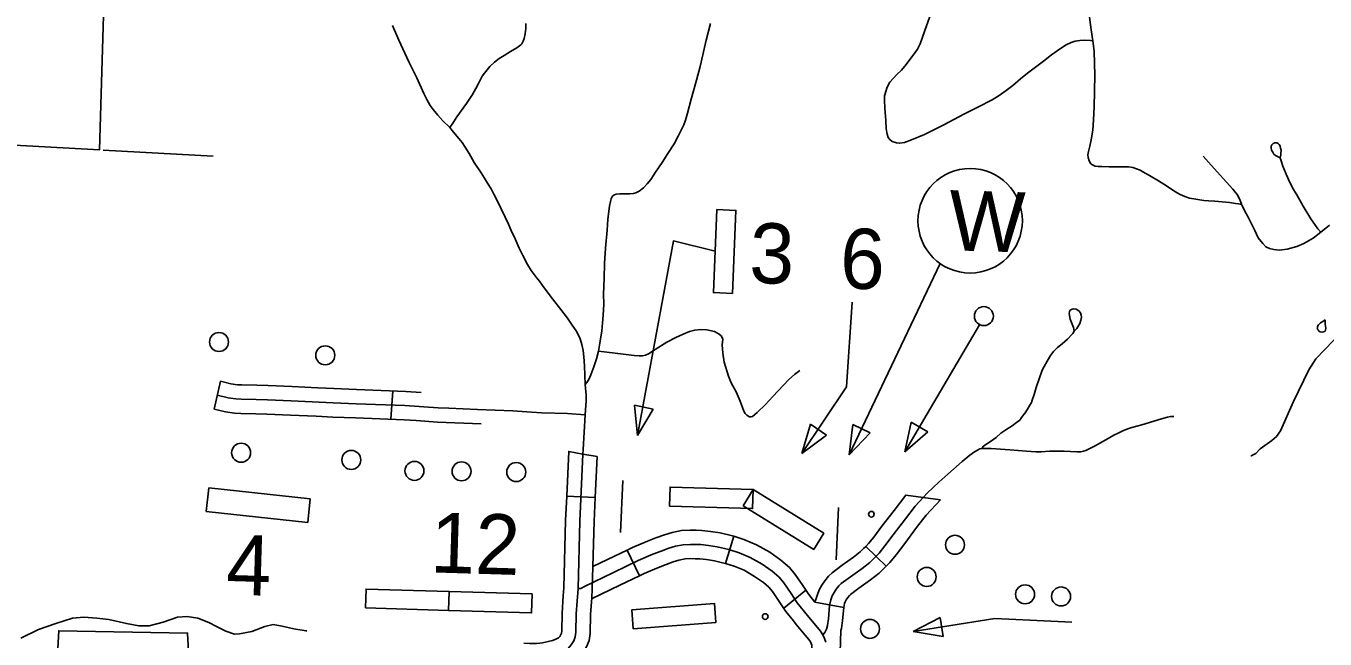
# Model space of a CAD drawing. Extents: x 653372 to 905732, y 627442 to 787275.
# Drawn here: x 690999 to 697843, y 760924 to 764152 of the extents above; entities that cross this region are included whole.
import ezdxf

# ---------------------------------------------------------------- set-up
doc = ezdxf.new("R2010")
doc.units = 0
for name, color, linetype in [('31', 7, 'Continuous'), ('32', 7, 'Continuous'), ('35', 7, 'Continuous'), ('45', 7, 'Continuous'), ('5', 7, 'Continuous'), ('56', 7, 'Continuous'), ('57', 7, 'Continuous'), ('6', 7, 'Continuous')]:
    doc.layers.add(name, color=color, linetype=linetype)

msp = doc.modelspace()

# ---------------------------------------------------------------- linework, layer by layer
at = {"layer": '31'}
msp.add_line((693848.6, 761677.2), (693998.4, 761670.3), dxfattribs=at)
for points in [[(696620.4, 764073.4), (696607.2, 764075.7), (696574.6, 764078.2), (696552.3, 764076.6), (696527.7, 764072.1), (696505.9, 764065.4), (696478.8, 764052.8), (696450, 764033.6), (696402.9, 764000.8), (696359.6, 763966.5), (696310.9, 763930), (696276.7, 763904.3), (696239.4, 763873.5), (696199, 763839), (696163.3, 763811.9), (696126.9, 763786.9), (696090.5, 763764.3), (696013.6, 763725), (695943.1, 763689.9), (695831.3, 763630.1), (695733.3, 763581.8), (695664.1, 763552.7), (695627.3, 763539.6), (695601.9, 763534.5), (695585.6, 763536.4), (695563.6, 763544.5), (695551.2, 763553.8), (695542.6, 763564.5), (695535.7, 763582.5), (695532.1, 763610.1), (695529, 763655.5), (695523.5, 763719.6), (695521.8, 763762), (695523.2, 763784.3), (695529.9, 763807.8), (695537.2, 763829.9), (695551.4, 763857), (695587.5, 763896.8), (695612.7, 763920.5), (695636.6, 763948.8), (695662.1, 763982.2), (695679.2, 764005), (695695.5, 764030.5), (695709.7, 764059), (695734, 764123.7), (695761.6, 764201.6)], [(696599.3, 764224.9), (696612, 764131.4), (696620.4, 764073.4), (696626.3, 764018.9), (696629.2, 763955.2), (696630.5, 763893), (696626.6, 763727.1), (696623.5, 763658.2), (696619.2, 763603.2), (696610.7, 763552.7), (696604.3, 763519.2), (696597, 763490.7), (696594.4, 763474.2), (696595.6, 763460.2), (696601, 763443), (696609.6, 763426.7), (696618, 763421), (696631.7, 763414.2), (696648.2, 763412.7), (696666.9, 763411.6), (696706.4, 763410.9), (696783.7, 763411.3), (696808.8, 763410), (696830.1, 763406.7), (696849.7, 763400.7), (696869.2, 763393.2), (696884, 763384.7), (696918.7, 763365.5), (696965.4, 763336.2), (697007.5, 763311.2), (697051.5, 763281.5), (697080.4, 763264.6), (697104.1, 763253.7), (697129.8, 763246.5), (697163.3, 763240.2), (697204.3, 763234.1), (697229.4, 763231.2), (697262.5, 763229.1), (697301.4, 763226.4), (697339.3, 763222.6), (697371.8, 763217.8), (697387.4, 763215.5), (697395.9, 763214.2), (697403.2, 763214.8)], [(692930.7, 764154.9), (692964.1, 764077.8), (693017.3, 763963.5), (693058.4, 763879.9), (693095.8, 763797.6), (693112, 763765.6), (693129.6, 763733.5), (693144.3, 763712.6), (693168.9, 763683.6), (693194.9, 763652.6), (693231.7, 763617.7), (693251.1, 763593.4), (693279.4, 763560.5), (693297.7, 763539.1), (693314, 763513.7), (693333.5, 763480.6), (693361.3, 763433.8), (693396.8, 763379.4), (693414.9, 763350.6), (693431.8, 763325.2), (693449.9, 763294.5), (693463.5, 763267.6), (693482.8, 763230.4), (693502.4, 763189), (693524.2, 763145.7), (693541.2, 763109), (693555.5, 763075.2), (693576.4, 763031.4), (693597.2, 762982), (693616.9, 762942.9), (693642.5, 762897.2), (693661, 762864.1), (693687.8, 762829.4), (693704.8, 762808.5), (693729.4, 762773.2), (693772.7, 762714.8), (693816.5, 762659.2), (693851.8, 762613.2), (693876.2, 762577.1), (693897.6, 762547.8), (693912.1, 762521.4), (693920, 762504.8), (693927.9, 762475.8), (693934.4, 762444), (693938.9, 762410.5), (693941.2, 762362.1), (693945.7, 762264.8), (693950, 762208), (693950.4, 762175.8), (693949.4, 762155.2), (693945, 762104.3), (693935, 761922.7), (693933.8, 761897.8)], [(693633.6, 764165.9), (693632.8, 764138.9), (693629.9, 764111), (693624.5, 764086.2), (693619.3, 764072.8), (693612.2, 764058.9), (693607.3, 764052.9), (693585.2, 764037.4), (693551.5, 764017.5), (693518.5, 763997.5), (693492.4, 763980.8), (693467.5, 763961.3), (693443.9, 763939), (693415.8, 763904.7), (693402.5, 763887.4), (693393.9, 763871.4), (693383.8, 763849.4), (693370.2, 763823.5), (693352.4, 763792.3), (693320.6, 763744.7), (693269.1, 763673.3), (693251.5, 763646.1), (693231.7, 763617.7)], [(697867, 763102.9), (697821.9, 763065.8), (697780.9, 763035.7), (697732.5, 763007), (697694.7, 762990.7), (697644.4, 762977.9), (697601.4, 762972.1), (697573.7, 762974.5), (697551.7, 762980.7), (697531.4, 762989.3), (697515.2, 763006.4), (697491.5, 763036.5), (697472.9, 763075.9), (697437.7, 763145.1), (697419.8, 763181.4), (697403.2, 763214.8), (697393.7, 763238.5), (697381, 763264.2), (697358.1, 763292.7), (697323.5, 763329.4), (697243.4, 763419), (697202, 763466.2)], [(697843.3, 762605), (697844.1, 762582.8), (697847.4, 762561.2), (697846.3, 762551.4), (697842.1, 762544.3), (697835.7, 762541), (697827.7, 762539.2), (697818.2, 762541.1), (697810.8, 762545.7), (697806.7, 762551.8), (697802.8, 762557), (697803, 762563), (697804.4, 762569.7), (697809.8, 762577.8), (697819.3, 762588.7), (697832.2, 762596.6), (697843.3, 762605)], [(694008.3, 761886), (693933.8, 761897.8), (693859.4, 761912), (693848.6, 761677.2)], [(693908, 761190.5), (693917.6, 761545), (693933.8, 761897.8)], [(693998.4, 761670.3), (694008.3, 761886)], [(693830.1, 761151.3), (693833.1, 761194.1), (693842.6, 761547.8), (693848.6, 761677.2)], [(693979.8, 761141), (693982.9, 761187), (693992.5, 761542.3), (693998.4, 761670.3)], [(692564.8, 760837.9), (692592.5, 760840.5), (692646.4, 760843.5), (692695.7, 760846), (692731.5, 760845.6), (692839.5, 760842.9), (693047.8, 760839.5), (693324.6, 760833.8), (693650.7, 760826), (693691.9, 760826.1), (693714.6, 760828.1), (693733.9, 760830.8), (693767.3, 760837.8), (693794.8, 760844.3), (693816.9, 760852.2), (693839.9, 760863.5), (693856.1, 760875), (693872.6, 760893.8), (693885.2, 760915.3), (693893.1, 760935), (693896.5, 760959.5), (693898.8, 761057.4), (693908, 761190.5)], [(693618.6, 760751.7), (693649.9, 760751), (693695.3, 760751.1), (693723.1, 760753.5), (693746.8, 760756.9), (693783.6, 760764.6), (693816.2, 760772.3), (693846.3, 760783.1), (693878.2, 760798.8), (693906.6, 760818.8), (693933.7, 760849.7), (693952.8, 760882.2), (693966.2, 760915.6), (693971.4, 760953.5), (693973.8, 761054), (693979.8, 761141)], [(693622.1, 760901.7), (693651.6, 760901), (693688.6, 760901.1), (693706, 760902.6), (693721, 760904.7), (693751.1, 760911), (693773.4, 760916.3), (693787.6, 760921.4), (693801.5, 760928.2), (693805.7, 760931.2), (693811.6, 760937.9), (693817.7, 760948.4), (693820.1, 760954.4), (693821.7, 760965.5), (693823.9, 761060.9), (693830.1, 761151.3)]]:
    msp.add_lwpolyline(points, dxfattribs=at)
at = {"layer": '32'}
for p, q in [((694729, 761465), (694684.2, 761321.9)), ((694166.3, 761392.6), (694231.8, 761257.7)), ((695531, 761307.1), (695423.6, 761411.8)), ((695108.9, 761180.9), (694991.7, 761087.3)), ((695307.7, 761089.8), (695156.2, 761117.5))]:
    msp.add_line(p, q, dxfattribs=at)
for points in [[(694606.5, 764166), (694583.2, 764077.1), (694550.5, 763939.3), (694531.6, 763867.6), (694503.5, 763767), (694484.1, 763693.3), (694473.6, 763657.2), (694464.5, 763631.4), (694453.5, 763607.3), (694435.7, 763572.4), (694413.8, 763532.2), (694381.7, 763480.1), (694350.8, 763432.7), (694315.3, 763382.6), (694291.1, 763344.5), (694271.6, 763320.4), (694252.3, 763300.4), (694229.2, 763283.3), (694212.7, 763273.5), (694199.8, 763269.9), (694181.5, 763268), (694128.4, 763268.1), (694109.6, 763267.3), (694100.2, 763264.1), (694093.7, 763260.4), (694086.5, 763251.7), (694082.8, 763242), (694078.9, 763227.9), (694074.3, 763204.4), (694071, 763177.4), (694065.3, 763133.1), (694060.6, 763076.6), (694053.4, 762982.8), (694048.1, 762904.2), (694045.6, 762822.5), (694042.6, 762739.9), (694043, 762688.2), (694040.3, 762628.7), (694036.6, 762589), (694033.4, 762547.9), (694024.4, 762492.1), (694015.6, 762439.7), (694005.4, 762400.1), (693991.3, 762358), (693975.8, 762315.2), (693964.5, 762290.2), (693954.3, 762274.7), (693945.7, 762264.8)], [(696521.8, 762545.3), (696517.4, 762564.6), (696500.1, 762607.9), (696494.9, 762639.2), (696497, 762649), (696501.5, 762655.1), (696511, 762661.6), (696519.8, 762663.2), (696532.7, 762660.4), (696546.1, 762651.9), (696554.9, 762641.3), (696559.1, 762629.8), (696560, 762618.6), (696557.7, 762602.5), (696551.6, 762585.3), (696535.3, 762559.1), (696521.8, 762545.3)], [(696036.2, 761927.5), (696041.2, 761936.7), (696051.4, 761944.4), (696086.2, 761967.6), (696110.3, 761984.9), (696135.9, 762008.3), (696161.2, 762026.2), (696194.8, 762047.5), (696218.8, 762063.6), (696234.8, 762076.8), (696245.1, 762091.4), (696263.2, 762115), (696275.6, 762134.5), (696288.7, 762155.9), (696296.5, 762169.9), (696301.2, 762182.2), (696310.8, 762211.7), (696321.2, 762248), (696337.5, 762294.1), (696353.8, 762339.6), (696364.3, 762359.4), (696379.4, 762388.2), (696397.1, 762416.8), (696412.6, 762437.5), (696433.1, 762458.6), (696457.9, 762479), (696486.6, 762503.6), (696511.4, 762529.4), (696514.7, 762533.7), (696521.8, 762545.3)], [(695726.4, 761669.3), (695748.8, 761693.8), (695808.8, 761750.2), (695855.3, 761792.6), (695931.1, 761859.2), (695972.5, 761892.8), (695996.6, 761910.7), (696011.8, 761919.5), (696025.6, 761925.3), (696036.2, 761927.5), (696047.4, 761927.2), (696085.3, 761927.3), (696182.2, 761920.6), (696270.7, 761913.6), (696319.6, 761909.1), (696348.2, 761909.4), (696391.7, 761913.1), (696448.3, 761913.9), (696469.3, 761912.6), (696536.3, 761909.4), (696556.2, 761910.6), (696570.5, 761912.7), (696583.7, 761916.6), (696628.7, 761939.5), (696688.1, 761972.5), (696731.1, 761998.5), (696753.1, 762009), (696781.4, 762021.9), (696804.6, 762030.5), (696825.3, 762037.3), (696878.6, 762052.5), (696941.2, 762071.1), (696981.3, 762084.2), (697013.9, 762093.1), (697030.1, 762096.4), (697046.8, 762095.8)], [(695197.8, 760945.9), (695208, 760957.9), (695216.1, 760976.2), (695222.2, 760995.9), (695227, 761030.6), (695233.5, 761101.2), (695240, 761131.4), (695246.8, 761151.7), (695256.6, 761168.8), (695268.3, 761187), (695282.5, 761204.6), (695294.6, 761216.1), (695343.5, 761252.5), (695404.4, 761295.3), (695444.5, 761327.1), (695465.2, 761347.1), (695494.1, 761376.7), (695525, 761414.2), (695568.9, 761472.5), (695632.3, 761556.3), (695684.6, 761624.3), (695726.4, 761669.3)], [(695423.6, 761411.8), (695438.2, 761426.8), (695466.1, 761460.7), (695509.1, 761517.7), (695572.7, 761601.8), (695634.3, 761681.9), (695817.3, 761656.9)], [(695531, 761307.1), (695550, 761326.6), (695583.9, 761367.8), (695628.8, 761427.3), (695691.9, 761510.8), (695741.9, 761575.8), (695817.3, 761656.9)], [(694729, 761465), (694722.3, 761467.1), (694656.3, 761482.8), (694605.6, 761490.9), (694560.8, 761496), (694529.8, 761496.9), (694499.3, 761497.8), (694452.9, 761495.2), (694403.9, 761485.5), (694363, 761473.7), (694318.3, 761457.6), (694274.2, 761439.6), (694194.6, 761406.4), (694166.3, 761392.6)], [(695156.2, 761117.5), (695123.9, 761157.9), (695092.4, 761206.4), (695051.2, 761264.6), (695021.2, 761301.5), (694977.1, 761340.1), (694918.3, 761381.2), (694848.4, 761421), (694781.9, 761448.5), (694729, 761465)], [(695063, 761114), (695030.3, 761164.3), (694991.4, 761219.3), (694967.1, 761249.3), (694930.8, 761280.9), (694878.1, 761317.7), (694815.4, 761353.5), (694756.4, 761377.9), (694702.4, 761394.8), (694641.7, 761409.2), (694595.5, 761416.6), (694555.4, 761421.1), (694527.5, 761422), (694500.3, 761422.8), (694462.4, 761420.6), (694421.6, 761412.5), (694386.1, 761402.3), (694345.2, 761387.6), (694302.8, 761370.2), (694225.4, 761338), (694095.3, 761274.8), (693941.7, 761201), (693922.1, 761191), (693908, 761190.5)], [(694166.3, 761392.6), (694062.7, 761342.3), (693986.1, 761305.6)], [(695156.2, 761117.5), (695178, 761182.6), (695192.5, 761207.7), (695207.4, 761231), (695227.3, 761255.7), (695246.4, 761273.6), (695299.5, 761313.2), (695359.5, 761355.5), (695395, 761383.6), (695412.3, 761400.3), (695423.6, 761411.8)], [(694684.2, 761321.9), (694682.5, 761322.4), (694627.1, 761335.6), (694585.3, 761342.3), (694550.1, 761346.2), (694525.3, 761347), (694501.4, 761347.7), (694471.9, 761346), (694439.3, 761339.6), (694409.2, 761330.9), (694372, 761317.5), (694331.4, 761300.9), (694256.3, 761269.6), (694231.8, 761257.7)], [(695042.7, 761019.2), (695002.2, 761070), (694968.2, 761122.2), (694931.6, 761174), (694912.9, 761197), (694884.6, 761221.8), (694838, 761254.3), (694782.4, 761286), (694730.8, 761307.3), (694684.2, 761321.9)], [(695292.3, 760968.7), (695295.7, 760979.5), (695301.5, 761022), (695307.7, 761089.8), (695312.4, 761111.5), (695315.5, 761120.7), (695320.7, 761129.8), (695329.2, 761143.1), (695337.7, 761153.5), (695342.9, 761158.5), (695387.5, 761191.7), (695449.3, 761235.2), (695493.9, 761270.5), (695518.1, 761293.9), (695531, 761307.1)], [(694231.8, 761257.7), (694127.9, 761207.3), (693979.4, 761135.9)], [(695212.6, 760907.9), (695206.3, 760927.5), (695197.8, 760945.9), (695185.2, 760965.7), (695116, 761047.7), (695063, 761114)], [(695126.2, 760578.7), (695131, 760686.3), (695138.9, 760858.5), (695139.7, 760885.2), (695139, 760892), (695136.3, 760900.1), (695131.8, 760909.8), (695124.6, 760921.2), (695058, 761000.1), (695042.7, 761019.2)], [(695276.1, 760572.1), (695280.8, 760679.5), (695288.8, 760852.8), (695292.3, 760968.7)]]:
    msp.add_lwpolyline(points, dxfattribs=at)
at = {"layer": '35'}
for points in [[(697934.2, 762543.4), (697795.8, 762399.3), (697757.6, 762341.9), (697677.3, 762175.4), (697608.8, 762020), (697587.3, 761991.3), (697563.7, 761969.8), (697501.3, 761925.1), (697479.2, 761901.9), (697453.4, 761889.3), (697452, 761889.1)], [(692479.2, 760967), (692475.2, 760966.7), (692410.4, 760978.7), (692349, 760992.2), (692302.5, 761000.3), (692257.1, 760990), (692189.5, 760963.6), (692124, 760952.2), (692097.2, 760949.6), (692052.6, 760966), (692003.2, 760990.9), (691962, 761010.5), (691904.3, 761034), (691849.4, 761042.3), (691798.4, 761038.8), (691722.4, 761012.7), (691648.4, 760993.2), (691594.9, 760993.1), (691528.5, 761005.1), (691435.6, 761026.3), (691372.4, 761034.9), (691304, 761038.6), (691245.4, 761033.7), (691156.1, 761006.3), (691064.9, 760974), (690971.7, 760928.3)]]:
    msp.add_lwpolyline(points, dxfattribs=at)
at = {"layer": '45'}
for p, q in [((691990.5, 762135.1), (692023.5, 762281.4)), ((692921.7, 762081.1), (692931.8, 762230.8))]:
    msp.add_line(p, q, dxfattribs=at)
for points in [[(697607.5, 763458.2), (697595.9, 763462.6), (697582.1, 763470.7), (697574.2, 763478.2), (697567.7, 763487.4), (697562.2, 763497.9), (697559.4, 763509.3), (697559.7, 763520.1), (697563.5, 763526.8), (697570.1, 763534.3), (697579.6, 763537.2), (697589.1, 763536.9), (697596.7, 763533.9), (697602.4, 763527.9), (697606.6, 763520.1), (697609.5, 763509.6), (697611.9, 763498.3), (697611.4, 763482.5), (697609.8, 763473.5), (697607.5, 763458.2)], [(697607.5, 763458.2), (697611.5, 763442.2), (697621.1, 763414.8), (697637.8, 763371.4), (697658.2, 763327.9), (697677.4, 763292.1), (697694.6, 763263.2), (697728.5, 763203.6), (697768.9, 763136.5), (697804.8, 763084.4), (697821.9, 763065.8)], [(694015.6, 762439.7), (694104.3, 762429.8), (694204.2, 762417.4), (694229.4, 762414.7), (694247.4, 762415.5), (694264.1, 762419), (694278.9, 762425.2), (694314.8, 762448), (694376.4, 762486.7), (694423.6, 762511.9), (694461.4, 762530), (694495, 762543.6), (694523.1, 762550.7), (694552.8, 762553.8), (694587.2, 762551.5), (694626.8, 762543), (694651.7, 762530.3), (694661.4, 762520.7), (694667.7, 762511.8), (694670.1, 762502.5), (694667.2, 762472.7), (694669.9, 762430), (694678.5, 762382.6), (694700.8, 762308.2), (694715, 762272.5), (694740.2, 762225.9), (694762.6, 762176.1), (694781, 762123.8), (694787.9, 762111.6), (694797.6, 762103.4), (694812, 762094.3), (694820.7, 762094.3), (694827.3, 762096.5), (694851.9, 762117.7), (694895.6, 762159.5), (694934.7, 762200.9), (695018.9, 762290), (695048.9, 762317), (695076.8, 762338.7)], [(692023.5, 762281.4), (692079.4, 762268.8), (692113.2, 762263.6), (692136.8, 762262.3), (692214.9, 762260.7), (692274.6, 762258.9), (692400.1, 762253.5), (692536.3, 762246.9)], [(692007, 762208.3), (692065.4, 762195.1), (692105.3, 762189), (692133.8, 762187.3), (692213, 762185.7), (692271.8, 762184), (692396.7, 762178.6), (692618.6, 762167.8), (692738.2, 762163.4), (692996.1, 762153.2), (693171.9, 762141.4), (693227.1, 762139.3)], [(692536.3, 762246.9), (692621.8, 762242.8), (692741.1, 762238.4), (693000.1, 762228.1), (693081.9, 762222.6)], [(691990.5, 762135.1), (692051.5, 762121.3), (692097.4, 762114.3), (692130.9, 762112.3), (692211.2, 762110.8), (692269.1, 762109), (692393.2, 762103.7), (692529.1, 762097.1)], [(693227.1, 762139.3), (693377.5, 762133.6), (693564, 762125.6), (693663.5, 762119.3), (693716.5, 762116.1), (693852.8, 762111.2), (693945, 762104.3)], [(692529.1, 762097.1), (692615.4, 762092.9), (692735.3, 762088.5), (692992.1, 762078.3), (693055.1, 762074.1)], [(693055.1, 762074.1), (693167.9, 762066.5), (693397.4, 762057.8)]]:
    msp.add_lwpolyline(points, dxfattribs=at)
at = {"layer": '5'}
for points in [[(691986.3, 763467.3), (691406.3, 763498.8)], [(695280.4, 761617.4), (695268.2, 761341.2)]]:
    msp.add_lwpolyline(points, dxfattribs=at)
at = {"layer": '56'}
for p, q in [((694221.9, 761995.9), (694204.7, 762156.2)), ((694204.7, 762156.2), (694304.3, 762134.5)), ((694304.3, 762134.5), (694221.9, 761995.9)), ((695629.1, 761909.3), (695662.8, 762067)), ((695662.8, 762067), (695750.6, 762015.3)), ((695087, 761900.9), (695132.6, 762055.5)), ((695216.3, 761997.2), (695087, 761900.9)), ((695132.6, 762055.5), (695216.3, 761997.2)), ((695750.6, 762015.3), (695629.1, 761909.3)), ((695673.1, 760963.9), (695816.3, 761038.1)), ((695816.3, 761038.1), (695832.2, 760937.3)), ((695832.2, 760937.3), (695673.1, 760963.9))]:
    msp.add_line(p, q, dxfattribs=at)
for points in [[(694640, 763185.4), (694739.9, 763181.1), (694721, 762744), (694621.1, 762748.3)], [(694390, 761624), (694393, 761723.9), (694830.3, 761710.8), (694827.3, 761610.8)], [(694777.8, 761625.7), (694830.3, 761710.8), (695202.6, 761480.9), (695150, 761395.9)], [(692788.5, 761087.6), (692791.5, 761187.5), (693228.8, 761174.4), (693225.8, 761074.4)], [(693225.8, 761074.4), (693228.8, 761174.4), (693666.1, 761161.3), (693663.1, 761061.3)], [(694198.3, 760977.7), (694190.5, 761077.4), (694626.7, 761111.5), (694634.5, 761011.8)]]:
    msp.add_lwpolyline(points, close=True, dxfattribs=at)
for points in [[(694630.5, 762966.8), (694410.6, 763020.7), (694221.9, 761995.9)], [(695352.4, 762698.1), (695322.9, 762252.6), (695087, 761900.9)], [(696022.8, 762578.1), (695629.1, 761909.3)], [(694143.9, 761758.1), (694132.1, 761486)], [(695673.1, 760963.9), (696104.3, 761031.7), (696508.9, 761012.9)]]:
    msp.add_lwpolyline(points, dxfattribs=at)
for centre, radius in [((696046, 762624.7), 50), ((692016.3, 762488.2), 50), ((692576.4, 762418.2), 50), ((692133, 761905.3), 50), ((692713.4, 761867.2), 50), ((693046, 761809.6), 50), ((693294.3, 761807.2), 50), ((693582.5, 761803.5), 50), ((695453.3, 761581.4), 15), ((695893.9, 761420.3), 50), ((695744.8, 761251.1), 50), ((696263.1, 761159.6), 50), ((696452.7, 761148.2), 50), ((695446, 760977.5), 50)]:
    msp.add_circle(centre, radius, dxfattribs=at)
at = {"layer": '57'}
for p, q in [((695335.8, 761893.3), (695355.5, 762053.4)), ((695447.6, 762009.5), (695335.8, 761893.3)), ((695355.5, 762053.4), (695447.6, 762009.5)), ((691963, 761720.4), (691949.4, 761596.1)), ((692497.3, 761662), (691963, 761720.4)), ((692483.7, 761537.7), (692497.3, 761662)), ((691949.4, 761596.1), (692483.7, 761537.7))]:
    msp.add_line(p, q, dxfattribs=at)
msp.add_lwpolyline([(695815.8, 762901.6), (695335.8, 761893.3)], dxfattribs=at)
for centre, radius in [((695973.9, 763126.6), 275), ((694894.2, 761042.6), 15)]:
    msp.add_circle(centre, radius, dxfattribs=at)
at = {"layer": '6'}
for points in [[(692625.6, 764780.2), (691426.8, 764857.3), (691386.4, 763499.9), (690104.8, 763569.7), (690138.8, 764932), (688620.9, 764953.1)], [(690883, 759053.9), (691057, 759315), (691093, 759457.9), (691119.5, 759974.4), (691160.2, 760748.8), (691172.2, 760968.2), (691851, 760955.7), (691858.8, 760792)]]:
    msp.add_lwpolyline(points, dxfattribs=at)

# ---------------------------------------------------------------- texts
at = {"layer": '56'}
for s, p in [('3', (694807.4, 762800.1)), ('6', (695284.9, 762771.8)), ('12', (693126.7, 761275.3))]:
    msp.add_text(s, height=316.8, rotation=358.28003, dxfattribs=at).set_placement(p)
at = {"layer": '57'}
for s, p in [('W', (695858.2, 762971.6)), ('4', (692051.8, 761158.5))]:
    msp.add_text(s, height=316.8, rotation=358.28003, dxfattribs=at).set_placement(p)

doc.saveas('drawing.dxf')
